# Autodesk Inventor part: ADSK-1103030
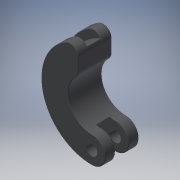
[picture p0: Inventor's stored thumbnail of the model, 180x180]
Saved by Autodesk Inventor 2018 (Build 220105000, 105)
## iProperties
Shininess: 41.0
Length Units: 11272
Angle Units: 11279
Time Units: 11290
Mass Units: 11286
Length Display Precision: 4
Angle Display Precision: 2
Compacted: True
Created: 2000-08
Part Number: ADSK-1103030
Document SubType Name: Modeling
Description: CLUTCH SHOE
Mass: 2.36913 g
Surface Area: 6.11189 cm^2
Volume: 0.525306 cm^3
Density: 4.51 g/cm^3
Material: Titanium
Appearance: Black
Density: 0.0
Volumn: 0.0
Area: 0.0
PropertySet Name: Model Information
Control State: 0
Master: False
Checked Out: False
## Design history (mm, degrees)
node "Extrusion1" dims "d5" = 6.35, "d6" = 0
  sketch "Sketch3"
    geometry: L1 (0, -6.985)-(0, 6.985); L2 (-2.54, 3.648)-(-2.54, 9.18); C1 r 1.048 at (0, -6.985); A1 r 2.54 centre (0, -6.985) between (0, -9.525) and (0, -4.445); A2 r 9.525 centre (0, 0) between (-2.54, 9.18) and (0, -9.525); A3 r 4.445 centre (0, 0) between (-2.54, 3.648) and (0, -4.445); 3 further points
    constraints: 6 point on circle, 5 coincident, 4 centre point, 4 end point, 1 midpoint, 1 parallel, 1 point on line, 1 tangent, 1 vertical
    dimensions: "d0" = 2.0955 diameter of C1; "d4" = 9.525 radius of A2; "d18" = 8.89 diameter of A3; "d19" = 2.54 distance between parallel lines of L1 L2; "d20" = 2.54 radius of A1 (derived)
node "Fillet1" dims "d7" = 1.5875
node "Fillet2" dims "d10" = 1.5875
workplane "Work Plane1"
node "Extrusion2" dims "d12" = 2.54, "d13" = 0
  sketch "Sketch4"
    geometry: C1 r 2.857 at (0, -6.985); 3 further points
    constraints: 1 centre point, 1 coincident, 1 other
    dimensions: "d11" = 5.715 diameter of C1
node "Extrusion3" dims "d14" = 0, "d15" = 0
  sketch "Sketch5"
    geometry: L1 (0, 0)-(1.309, 0) reference; C1 r 1.048 at (0, -6.985) reference; C2 r 8.033 at (0, 0); A1 r 9.525 centre (0, 0) between (0, -9.525) and (1.524, -9.402) reference; 3 further points
    constraints: 2 coincident, 1 centre point, 1 tangent, 5 other
node "Fillet3" dims "d16" = 0.381
node "Fillet4" dims "d17" = 0.127
workaxis "Work Axis1"
body "Solid1"
other parameters: "d1" = 5.08
